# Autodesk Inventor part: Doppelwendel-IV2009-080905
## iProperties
Created: 2008-09
Part Number: Doppelwendel-IV2009-080905
Document SubType Name: Modeling
Designer: rs44
Density: 1 g/cm^3
Author: rs44
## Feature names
1. Spirale2
2. Runde Anordnung1 [Circular Pattern]
3. Rechteckige Anordnung1 [Rectangular Pattern]
